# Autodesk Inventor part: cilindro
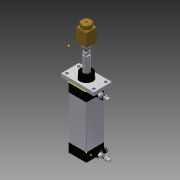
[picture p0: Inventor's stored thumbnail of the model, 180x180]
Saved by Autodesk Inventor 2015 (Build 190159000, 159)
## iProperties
Created: 2016-06
Part Number: cilindro
Material: Aluminio 6061
Document SubType Name: Modeling
Designer: Diego
Density: 2.7 g/cm^3
Appearance: Aluminio - Plano
Author: Diego
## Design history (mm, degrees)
sketch "Boceto1"
  geometry: L1 (2, 0)-(58, 0); L2 (60, 2)-(60, 58); L3 (58, 60)-(2, 60); L4 (0, 58)-(0, 2); A1 r 2 centre (2, 58) between (2, 60) and (0, 58); A2 r 2 centre (58, 58) between (60, 58) and (58, 60); A3 r 2 centre (58, 2) between (58, 0) and (60, 2); A4 r 2 centre (2, 2) between (0, 2) and (2, 0); 4 further points
  constraints: 8 end point, 8 point on circle, 8 point on line, 8 tangent, 4 centre point, 3 equal radius, 2 parallel, 1 horizontal, 1 perpendicular
  dimensions: "d0" = 60 distance of point (0, 60) point (60, 60); "d1" = 60 distance of point (60, 60) point (60, 0); "d2" = 2 radius of A1
extrude "Extrusión1" new body sketch "Boceto1" distance "d3" = 145; taper "d4" = 0 deg
sketch "Boceto2"
  geometry: L1 (-0.3, -0.301)-(60.158, -0.301); L2 (60.158, -0.301)-(60.158, 60.103); L3 (60.158, 60.103)-(-0.3, 60.103); L4 (-0.3, 60.103)-(-0.3, -0.301); 1 further point
  constraints: 8 end point, 2 parallel, 1 horizontal, 1 perpendicular
extrude "Extrusión2" join sketch "Boceto2" distance "d5" = 30; taper "d6" = 0 deg
fillet "Empalme1" dims "d7" = 2
sketch "Boceto3"
  geometry: L1 (0.3, 58.103)-(0.3, 1.699) reference; L2 (-58.158, 60.103)-(-1.7, 60.103) reference; L3 (-60.158, 1.699)-(-60.158, 58.103) reference; L4 (-1.7, -0.301)-(-58.158, -0.301) reference; A1 r 2 centre (-1.7, 58.103) between (0.3, 58.103) and (-1.7, 60.103) reference; A2 r 2 centre (-58.158, 1.699) between (-60.158, 1.699) and (-58.158, -0.301) reference; A3 r 2 centre (-1.7, 1.699) between (-1.7, -0.301) and (0.3, 1.699) reference; A4 r 2 centre (-58.158, 58.103) between (-58.158, 60.103) and (-60.158, 58.103) reference; 1 further point
extrude "Extrusión3" join sketch "Boceto3" distance "d8" = 30; taper "d9" = 0 deg
sketch "Boceto4"
  geometry: L1 (-58, 2)-(-2, 58); L2 (-2, 58)-(-2, 2); L3 (0, 2)-(0, 58) reference; L4 (-2, 2)-(-58, 58); C1 r 20 at (-30, 30); A1 r 2 centre (-58, 2) between (-60, 2) and (-58, 0) reference; A2 r 2 centre (-2, 58) between (0, 58) and (-2, 60) reference; 1 further point
  constraints: 6 end point, 1 centre point, 1 midpoint, 1 parallel, 1 perpendicular
  dimensions: "d10" = 40 diameter of C1
extrude "Extrusión4" join sketch "Boceto4" distance "d11" = 5; taper "d12" = 0 deg
sketch "Boceto5"
  geometry: L1 (-2, 2)-(-58, 2); L2 (-58, 2)-(-58, 58); L3 (-58, 58)-(-2, 58); L4 (-2, 58)-(-2, 2); C1 r 5 at (-52.028, 7.972); C2 r 5 at (-52.61, 52.61); C3 r 5 at (-7.972, 7.972); C4 r 5 at (-7.972, 52.028); 1 further point
  constraints: 8 end point, 4 centre point, 2 parallel, 1 horizontal, 1 perpendicular
  dimensions: "d13" = 10 diameter of C1; "d14" = 10 diameter of C2; "d15" = 10 diameter of C3; "d16" = 10 diameter of C4
hole "Agujero1" sketch "Boceto5" at (-52.028, 7.972), (-52.61, 52.61), (-7.972, 52.028), (-7.972, 7.972) diameter "d17" = 6.647; stored, may be unused: countersink angle "d21" = 90 deg, drill point angle "d23" = 0 deg; dims "d18" = 16, "d19" = 4, "d20" = 2, "d22" = 22.2
sketch "Boceto6"
  geometry: L1 (1.7, -0.301)-(58.158, -0.301) reference; L2 (2, 60)-(58, 60) reference; 1 further point
sketch "Boceto7"
  geometry: L1 (-24.998, 0)-(85.002, 0); L2 (85.002, 0)-(85.002, 60); L3 (85.002, 60)-(-24.998, 60); L4 (-24.998, 60)-(-24.998, 0); L5 (85.002, 0)-(85.002, 10); L6 (-24.998, 10)-(-24.998, 50); L7 (85.002, 60)-(75.002, 60); L8 (-24.998, 0)-(-14.998, 0); C1 r 5 at (75.002, 10); C2 r 5 at (-14.998, 10); C3 r 5 at (75.002, 50); C4 r 5 at (-14.998, 50); C5 r 22.5 at (30.002, 30); 1 further point
  constraints: 16 end point, 5 centre point, 5 point on line, 2 parallel, 1 horizontal, 1 perpendicular
  dimensions: "d26" = 110 distance of L3.end L2.end; "d27" = 10 distance of L1.end L5.end; "d28" = 40 distance of L6.start L6.end; "d29" = 10 distance of L2.end L7.end; "d30" = 10 distance of L1.start L8.end; "d31" = 10 diameter of C1; "d32" = 10 diameter of C2; "d33" = 10 diameter of C3; "d34" = 10 diameter of C4; "d35" = 45 diameter of C5
extrude "Extrusión5" join sketch "Boceto7" distance "d36" = 12; taper "d37" = 0 deg
sketch "Boceto8"
  geometry: C1 r 20 at (0, 0); 1 further point
  constraints: 1 centre point
  dimensions: "d38" = 40 diameter of C1
extrude "Extrusión6" join sketch "Boceto8" distance "d39" = 30; taper "d40" = 0 deg
sketch "Boceto9"
  geometry: 1 further point
sketch "Boceto10"
  geometry: C1 r 10 at (0, 0); 1 further point
  constraints: 1 centre point
  dimensions: "d41" = 20 diameter of C1
extrude "Extrusión7" join sketch "Boceto10" distance "d42" = 50; taper "d43" = 0 deg
sketch "Boceto11"
  geometry: L1 (0, 8)-(6, 8); L2 (0, 8)-(-6, 8); L3 (-6, 8)-(-6, -8); L4 (-6, -8)-(6, -8); L5 (6.041, 7.969)-(6, -8); C1 r 10 at (0, 0); A1 r 10 centre (0, 0) between (-6, -8) and (6.041, 7.969) reference; 2 further points
  constraints: 10 end point, 5 point on circle, 1 centre point, 1 coincident, 1 horizontal, 1 perpendicular, 2 other
extrude "Extrusión8" join sketch "Boceto11" distance "d47" = 10; taper "d48" = 0 deg
fillet "Empalme2" dims "d49" = 2
fillet "Empalme3" dims "d50" = 2
sketch "Boceto12"
  geometry: C1 r 6.02 at (0, 0); 1 further point
  constraints: 1 centre point
extrude "Extrusión9" join sketch "Boceto12" distance "d51" = 15; taper "d52" = 0 deg
feature "Rosca1" dims "d53" = 10, "d54" = 0
sketch "Boceto13"
  geometry: 1 further point
sketch "Boceto14"
  geometry: L1 (6.128, 12.588)-(13.965, 0.987); L2 (13.965, 0.987)-(7.837, -11.601); L3 (7.837, -11.601)-(-6.128, -12.588); L4 (-6.128, -12.588)-(-13.965, -0.987); L5 (-13.965, -0.987)-(-7.837, 11.601); L6 (-7.837, 11.601)-(6.128, 12.588); A1 r 14 centre (0, 0) between (6.128, 12.588) and (13.965, 0.987); 1 further point
  constraints: 12 end point, 6 point on circle, 1 centre point
  dimensions: "d56" = 28 diameter of A1; "d57" = 14 distance of L1.start L1.end; "d58" = 14 distance of L1.end L2.end; "d59" = 14 distance of L2.end L3.end; "d60" = 14 distance of L3.end L4.end; "d61" = 14 distance of L4.end L5.end
extrude "Extrusión10" join sketch "Boceto14" distance "d62" = 8; taper "d63" = 0 deg
fillet "Empalme4" dims "d64" = 0.5
sketch "Boceto15"
  geometry: C1 r 15.5 at (0, 0); 1 further point
  constraints: 1 centre point
  dimensions: "d65" = 31 diameter of C1
extrude "Extrusión11" join sketch "Boceto15" distance "d66" = 2; taper "d67" = 0 deg
sketch "Boceto16"
  geometry: L1 (0, -17.5)-(17.5, -17.5); L2 (17.5, -17.5)-(17.5, 17.5); L3 (17.5, 17.5)-(-17.5, 17.5); L4 (-17.5, 17.5)-(-17.5, -17.5); L5 (-17.5, -17.5)-(0, -17.5); 1 further point
  constraints: 10 end point, 2 perpendicular, 1 point on line
  dimensions: "d69" = 17.5 distance of L1.start L1.end; "d70" = 35 distance of L1.end L2.end; "d71" = 35 distance of L2.end L3.end; "d72" = 35 distance of L3.end L4.end
extrude "Extrusión12" join sketch "Boceto16" distance "d73" = 45; taper "d74" = 0 deg
chamfer "Chaflán1" distance "d75" = 2; stored, may be unused: second distance "d76" = 2, angle "d77" = 45 deg
sketch "Boceto17"
  geometry: C1 r 15.831 at (0, 0); 1 further point
  constraints: 1 centre point
extrude "Extrusión13" join sketch "Boceto17" distance "d78" = 14; taper "d79" = 0 deg
chamfer "Chaflán2" distance "d80" = 2; stored, may be unused: second distance "d81" = 2, angle "d82" = 45 deg
sketch "Boceto18"
  geometry: 2 further points
hole "Agujero2" sketch "Boceto18" at (0, 0) diameter "d83" = 4.917; stored, may be unused: countersink angle "d87" = 90 deg, drill point angle "d89" = 0 deg; dims "d84" = 12, "d85" = 4, "d86" = 2, "d88" = 17.1
sketch "Boceto19"
  geometry: 2 further points
hole "Agujero3" sketch "Boceto19" at (17.5, 20.044) diameter "d90" = 4.917; stored, may be unused: countersink angle "d94" = 90 deg, drill point angle "d96" = 0 deg; dims "d91" = 12, "d92" = 4, "d93" = 2, "d95" = 17.1
sketch "Boceto20"
  geometry: L1 (-30, -1.699)-(0, 58.404); L2 (0, 58.404)-(-30, 58.404); L3 (-30, 58.404)-(0, 58.404) reference; L4 (-30, 58.404)-(0, -2); C1 r 9 at (-15, 28.202); 1 further point
  constraints: 6 end point, 1 centre point, 1 collinear, 1 midpoint
  dimensions: "d97" = 18 diameter of C1
extrude "Extrusión14" join sketch "Boceto20" distance "d98" = 15; taper "d99" = 0 deg
sketch "Boceto21"
  geometry: 1 further point
sketch "Boceto22"
  geometry: L1 (-3.033, -7.403)-(-7.928, -1.074); L2 (-7.928, -1.074)-(-4.894, 6.328); L3 (-4.894, 6.328)-(3.033, 7.403); L4 (3.033, 7.403)-(7.928, 1.074); L5 (7.928, 1.074)-(4.894, -6.328); L6 (4.894, -6.328)-(-3.033, -7.403); 1 further point
  constraints: 12 end point
  dimensions: "d101" = 8 distance of L1.start L1.end; "d102" = 8 distance of L1.end L2.end; "d103" = 8 distance of L2.end L3.end; "d104" = 8 distance of L3.end L4.end; "d105" = 8 distance of L4.end L5.end
extrude "Extrusión15" join sketch "Boceto22" distance "d106" = 6; taper "d107" = 0 deg
fillet "Empalme5" dims "d108" = 0.5
sketch "Boceto23"
  geometry: C1 r 5 at (0, 0); 1 further point
  constraints: 1 centre point
  dimensions: "d109" = 10 diameter of C1
extrude "Extrusión16" join sketch "Boceto23" distance "d110" = 2; taper "d111" = 0 deg
sketch "Boceto24"
  geometry: C1 r 3 at (0, 0); 1 further point
  constraints: 1 centre point
  dimensions: "d112" = 6 diameter of C1
extrude "Extrusión17" join sketch "Boceto24" distance "d113" = 10; taper "d114" = 0 deg
feature "Rosca2" dims "d115" = 10, "d116" = 0
sketch "Boceto25"
  geometry: C1 r 7 at (0, 0); 1 further point
  constraints: 1 centre point
  dimensions: "d117" = 14 diameter of C1
extrude "Extrusión18" join sketch "Boceto25" distance "d118" = 3; taper "d119" = 0 deg
sketch "Boceto26"
  geometry: C1 r 5 at (0, 0); 1 further point
  constraints: 1 centre point
  dimensions: "d120" = 10 diameter of C1
extrude "Extrusión19" join sketch "Boceto26" distance "d121" = 10; taper "d122" = 0 deg
sketch "Boceto27"
  geometry: L1 (-2.785, -4.152)-(3.234, 3.813); L2 (2.785, 4.152)-(-3.234, -3.813); A1 r 5 centre (0, 0) between (-2.785, -4.152) and (3.234, 3.813) reference; 1 further point
  constraints: 4 end point, 4 point on circle, 1 parallel
extrude "Extrusión20" cut sketch "Boceto27" distance "d123" = 3; taper "d124" = 0 deg
node "Plano de trabajo1"
sketch "Boceto28"
  geometry: C1 r 6.5 at (15.148, -33.282); C2 r 4 at (15.148, -33.282); 1 further point
  constraints: 2 centre point, 1 coincident
  dimensions: "d125" = 13 diameter of C1; "d126" = 8 diameter of C2
extrude "Extrusión21" join sketch "Boceto28" distance "d127" = 3; taper "d129" = 0 deg; dims "d128" = 1.5, "d130" = 0
sketch "Boceto29"
  geometry: C1 r 7 at (0, 0); 1 further point
  constraints: 1 centre point
  dimensions: "d131" = 14 diameter of C1
extrude "Extrusión22" join sketch "Boceto29" distance "d132" = 10; taper "d133" = 0 deg
sketch "Boceto30"
  geometry: C1 r 5.823 at (0, 0); 1 further point
  constraints: 1 centre point
extrude "Extrusión23" join sketch "Boceto30" distance "d134" = 2; taper "d135" = 0 deg
sketch "Boceto31"
  geometry: C1 r 7.028 at (0, 0); 1 further point
  constraints: 1 centre point
extrude "Extrusión24" join sketch "Boceto31" distance "d136" = 2; taper "d137" = 0 deg
sketch "Boceto32"
  geometry: 2 further points
hole "Agujero4" sketch "Boceto32" at (0, 0) diameter "d138" = 6; stored, may be unused: countersink angle "d142" = 82 deg, drill point angle "d144" = 0 deg; dims "d139" = 6, "d140" = 3.023, "d141" = 2, "d143" = 3
sketch "Boceto33"
  geometry: 1 further point
sketch "Boceto34"
  geometry: L1 (30, 58.404)-(0, -1.699); L2 (30, -1.699)-(0, 58.404); C1 r 9 at (15, 28.352)
  constraints: 4 end point, 1 centre point, 1 midpoint
  dimensions: "d145" = 18 diameter of C1
extrude "Extrusión25" join sketch "Boceto34" distance "d146" = 15; taper "d147" = 0 deg
sketch "Boceto35"
  geometry: L1 (3.556, 7.166)-(7.984, 0.503); L2 (7.984, 0.503)-(4.428, -6.663); L3 (4.428, -6.663)-(-3.556, -7.166); L4 (-3.556, -7.166)-(-7.984, -0.503); L5 (-7.984, -0.503)-(-4.428, 6.663); L6 (-4.428, 6.663)-(3.556, 7.166); 1 further point
  constraints: 12 end point
  dimensions: "d149" = 8 distance of L1.start L1.end; "d150" = 8 distance of L1.end L2.end; "d151" = 8 distance of L2.end L3.end; "d152" = 8 distance of L3.end L4.end; "d153" = 8 distance of L4.end L5.end
extrude "Extrusión26" join sketch "Boceto35" distance "d154" = 6; taper "d155" = 0 deg
fillet "Empalme6" dims "d156" = 0.5
sketch "Boceto36"
  geometry: C1 r 5 at (0, 0); 1 further point
  constraints: 1 centre point
  dimensions: "d157" = 10 diameter of C1
extrude "Extrusión27" join sketch "Boceto36" distance "d158" = 2; taper "d159" = 0 deg
sketch "Boceto37"
  geometry: C1 r 4 at (0, 0); 1 further point
  constraints: 1 centre point
  dimensions: "d160" = 8 diameter of C1
extrude "Extrusión28" join sketch "Boceto37" distance "d161" = 12; taper "d162" = 0 deg
sketch "Boceto38"
  geometry: C1 r 7 at (0, 0); 1 further point
  constraints: 1 centre point
  dimensions: "d163" = 14 diameter of C1
extrude "Extrusión29" join sketch "Boceto38" distance "d164" = 4; taper "d165" = 0 deg
sketch "Boceto39"
  geometry: C1 r 5 at (0, 0); 1 further point
  constraints: 1 centre point
  dimensions: "d166" = 10 diameter of C1
extrude "Extrusión30" join sketch "Boceto39" distance "d167" = 10; taper "d168" = 0 deg
sketch "Boceto40"
  geometry: L1 (3.456, 3.613)-(-3.185, -3.855); L2 (-3.456, -3.613)-(3.185, 3.855); A1 r 5 centre (0, 0) between (3.456, 3.613) and (-3.185, -3.855) reference; 1 further point
  constraints: 4 end point, 4 point on circle
extrude "Extrusión31" cut sketch "Boceto40" distance "d169" = 3; taper "d170" = 0 deg
feature "Rosca3" dims "d171" = 10, "d172" = 0
node "Plano de trabajo2"
sketch "Boceto41"
  geometry: 1 further point
sketch "Boceto42"
  geometry: C1 r 4 at (17.055, -191.845); 1 further point
  constraints: 1 centre point
  dimensions: "d173" = 8 diameter of C1
extrude "Extrusión32" join sketch "Boceto42" distance "d174" = 3; taper "d176" = 0 deg; dims "d175" = 1.5, "d177" = 0
sketch "Boceto43"
  geometry: C1 r 7 at (0, 0); 1 further point
  constraints: 1 centre point
  dimensions: "d178" = 14 diameter of C1
extrude "Extrusión33" join sketch "Boceto43" distance "d179" = 10; taper "d180" = 0 deg
sketch "Boceto44"
  geometry: C1 r 6 at (0, 0); 1 further point
  constraints: 1 centre point
  dimensions: "d181" = 12 diameter of C1
extrude "Extrusión34" join sketch "Boceto44" distance "d182" = 2; taper "d183" = 0 deg
sketch "Boceto45"
  geometry: C1 r 7 at (0, 0); 1 further point
  constraints: 1 centre point
  dimensions: "d184" = 14 diameter of C1
extrude "Extrusión35" join sketch "Boceto45" distance "d185" = 2; taper "d186" = 0 deg
sketch "Boceto46"
  geometry: 2 further points
hole "Agujero5" sketch "Boceto46" at (0, 0) diameter "d187" = 6; stored, may be unused: countersink angle "d191" = 82 deg, drill point angle "d193" = 0 deg; dims "d188" = 6, "d189" = 3.023, "d190" = 2, "d192" = 3
chamfer "Chaflán3" distance "d194" = 1; stored, may be unused: second distance "d195" = 2, angle "d196" = 45 deg
chamfer "Chaflán4" distance "d197" = 1; stored, may be unused: second distance "d198" = 2, angle "d199" = 45 deg
sketch "Boceto47"
  geometry: 1 further point
node "Sólido1"
